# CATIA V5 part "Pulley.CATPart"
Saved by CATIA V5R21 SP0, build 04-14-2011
Part number: Pulley
Bounding box of the stored display mesh (mm): x -40.838 to 40.838, y -33 to 33, z -40.838 to 40.838
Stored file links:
  D:\CATIA V5R21 E-RESOURCES\CATIA-V5R21\catia-v5r21-Prts\c12_catia_v5r21_prt\c12_catia_v5r21figr_12-54 to 56\Pulley.CATPart
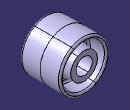
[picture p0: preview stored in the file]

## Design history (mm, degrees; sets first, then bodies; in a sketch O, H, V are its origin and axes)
Body1 (main body)
  Sketch1 on yz-plane, origin (0, 0, 0), H (0, 1, 0), V (0, 0, 1)
    line L1 (0, 13.45) -> (31.5, 13.45)
    point P1 (0, 13.45)
    point P2 (31.5, 13.45)
    line L2 (31.5, 13.45) -> (31.5, 22)
    point P3 (31.5, 22)
    line L3 (31.5, 22) -> (6, 24)
    point P4 (6, 24)
    line L4 (6, 24) -> (6, 33)
    point P5 (6, 33)
    line L5 (6, 33) -> (33, 35)
    point P6 (33, 35)
    line L6 (33, 35) -> (33, 41)
    point P7 (33, 41)
    line L7 (33, 41) -> (0, 41)
    point P8 (0, 41)
    point P9 (0, 41)
    point P10 (-33, 41)
    line L8 (-33, 41) -> (0, 41)
    point P11 (-33, 35)
    line L9 (-33, 35) -> (-33, 41)
    point P12 (-6, 33)
    line L10 (-6, 33) -> (-33, 35)
    point P13 (-6, 24)
    line L11 (-6, 24) -> (-6, 33)
    point P14 (-31.5, 22)
    line L12 (-31.5, 22) -> (-6, 24)
    point P15 (-31.5, 13.45)
    line L13 (-31.5, 13.45) -> (-31.5, 22)
    point P16 (0, 13.45)
    line L14 (0, 13.45) -> (-31.5, 13.45)
    length L1 = 31.5
    distance L1 H = 13.45
    distance P4 H = 24
    distance P3 H = 22
    distance L4 V = 6
    distance P5 H = 33
    distance P6 H = 35
    distance V L6 = 33
    distance L7 H = 41
    coincidence: P1 V, P8 V, P1 P16, P8 P9
    horizontal: L1 H, L7 H
    vertical: L2 V, L4 V, L6 V
    symmetry: P8 P9 V, P7 P10 V, L7 L8 V, P6 P11 V, L6 L9 V, P5 P12 V, L5 L10 V, P4 P13 V, L4 L11 V, P3 P14 V, L3 L12 V, P2 P15 V, L2 L13 V, P1 P16 V, L1 L14 V
  Shaft1: profile Sketch1, axis Sketch1.H, angle 360
  Fillet1: radius 3, on 4 faces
